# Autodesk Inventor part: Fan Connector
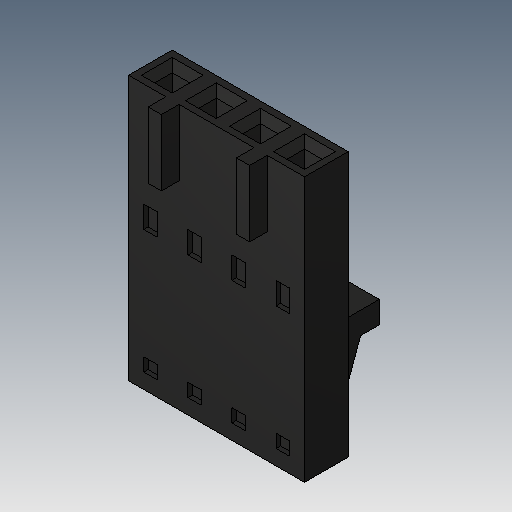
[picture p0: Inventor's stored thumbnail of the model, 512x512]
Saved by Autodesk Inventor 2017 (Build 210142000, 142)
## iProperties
Created: 2006-09
Part Number: Fan Connector
Material: Generic
Document SubType Name: Modeling
Designer: DanielSeverino
Density: 1 g/cm^3
Appearance: Default
Author: DanielSeverino
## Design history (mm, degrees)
feature "Solid1"
body "Solid2"
